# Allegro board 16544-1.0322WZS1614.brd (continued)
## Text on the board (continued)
User.36: ByImpedance:100.0@_REF_L1=("4.0/10.0(L2)" "3.5/7.0(L2)")|_REF_L6=("3.5/8.0(L5/L7)" "4.0/12.0(L5/L7)" "4.0/9.0(L4/L7)" "3.5/7.0(L4/L7)")|Type="DP"|_REF_L4=("4.0/9.0(L2/L5)" "3.5/7.0(L2/L5)")|_REF_L3=("3.5/8.0(L2/L4)" "4.0/9.0(L2/L5)" "3.5/7.0(L2/L5)" "4.0/12.0(L2/L4)")|imp="100.0"|_REF_L5=("4.0/9.0(L4/L7)" "3.5/7.0(L4/L7)")|_REF_L8=("4.0/10.0(L7)" "3.5/7.0(L7)") | ByImpedance:110.0@Type="DP"|imp="110.0" | ByImpedance:33.0@_REF_L1=("10.0(L2)")|_REF_L6=("10.5(L4/L7)" "9.5(L5/L7)")|Type="SE"|_REF_L4=("10.5(L2/L5)")|_REF_L3=("10.5(L2/L5)" "9.5(L2/L4)")|imp="33.0"|_REF_L5=("10.5(L4/L7)")|_REF_L8=("10.0(L7)") | ByImpedance:35.0@_REF_L1=("9.0(L2)")|_REF_L6=("8.5(L5/L7)" "9.5(L4/L7)")|Type="SE"|_REF_L4=("9.5(L2/L5)")|_REF_L3=("9.5(L2/L5)" "8.5(L2/L4)")|imp="35.0"|_REF_L5=("9.5(L4/L7)")|_REF_L8=("9.0(L7)") | ByImpedance:37.5@_REF_L1=("8.0(L2)")|_REF_L6=("7.5(L5/L7)" "8.5(L4/L7)")|Type="SE"|_REF_L4=("8.5(L2/L5)")|_REF_L3=("7.5(L2/L4)" "8.5(L2/L5)")|imp="37.5"|_REF_L5=("8.5(L4/L7)")|_REF_L8=("8.0(L7)") | ByImpedance:39.0@_REF_L1=("7.5(L2)")|_REF_L6=("7.0(L5/L7)" "8.0(L4/L7)")|Type="SE"|_REF_L4=("8.0(L2/L5)")|_REF_L3=("8.0(L2/L5)" "7.0(L2/L4)")|imp="39.0"|_REF_L5=("8.0(L4/L7)")|_REF_L8=("7.5(L7)") | ByImpedance:40.0@_REF_L1=("7.0(L2)")|_REF_L6=("7.5(L4/L7)" "6.5(L5/L7)")|Type="SE"|_REF_L4=("7.5(L2/L5)")|_REF_L3=("7.5(L2/L5)" "6.5(L2/L4)")|imp="40.0"|_REF_L5=("7.5(L4/L7)")|_REF_L8=("7.0(L7)") | ByImpedance:45.0@_REF_L1=("5.5(L2)")|_REF_L6=("5.0(L5/L7)" "6.0(L4/L7)")|Type="SE"|_REF_L4=("6.0(L2/L5)")|_REF_L3=("5.0(L2/L4)" "6.0(L2/L5)")|imp="45.0"|_REF_L5=("6.0(L4/L7)")|_REF_L8=("5.5(L7)") | ByImpedance:48.0@_REF_L1=("5.0(L2)")|_REF_L6=("5.0(L4/L7)" "4.5(L5/L7)")|Type="SE"|_REF_L4=("5.0(L2/L5)")|_REF_L3=("4.5(L2/L4)" "5.0(L2/L5)")|imp="48.0"|_REF_L5=("5.0(L4/L7)")|_REF_L8=("5.0(L7)") | ByImpedance:50.0@_REF_L1=("4.5(L2)")|_REF_L6=("4.0(L5/L7)" "4.5(L4/L7)")|Type="SE"|_REF_L4=("4.5(L2/L5)")|_REF_L3=("4.5(L2/L5)" "4.0(L2/L4)")|imp="50.0"|_REF_L5=("4.5(L4/L7)")|_REF_L8=("4.5(L7)") | ByImpedance:55.0@_REF_L1=("3.5(L2)")|_REF_L6=("3.5(L4/L7)")|Type="SE"|_REF_L4=("3.5(L2/L5)")|_REF_L3=("3.5(L2/L5)")|imp="55.0"|_REF_L5=("3.5(L4/L7)")|_REF_L8=("3.5(L7)") | ByImpedance:60.0@_REF_L1=("9.5/5.0(L2)")|_REF_L6=("9.5/5.0(L5/L7)" "10.0/5.0(L4/L7)")|Type="DP"|_REF_L4=("10.0/5.0(L2/L5)")|_REF_L3=("9.5/5.0(L2/L4)" "10.0/5.0(L2/L5)")|imp="60.0"|_REF_L5=("10.0/5.0(L4/L7)")|_REF_L8=("9.5/5.0(L7)") | ByImpedance:65.0@_REF_L1=("8.5/5.0(L2)")|_REF_L6=("8.5/5.0(L4/L7)" "8.0/5.0(L5/L7)")|Type="DP"|_REF_L4=("8.5/5.0(L2/L5)")|_REF_L3=("8.0/5.0(L2/L4)" "8.5/5.0(L2/L5)")|imp="65.0"|_REF_L5=("8.5/5.0(L4/L7)")|_REF_L8=("8.5/5.0(L7)") | ByImpedance:70.0@_REF_L1=("7.0/5.0(L2)")|_REF_L6=("7.0/5.0(L5/L7)" "7.5/5.0(L4/L7)")|Type="DP"|_REF_L4=("7.5/5.0(L2/L5)")|_REF_L3=("7.5/5.0(L2/L5)" "7.0/5.0(L2/L4)")|imp="70.0"|_REF_L5=("7.5/5.0(L4/L7)")|_REF_L8=("7.0/5.0(L7)") | ByImpedance:72.0@_REF_L1=("7.0/5.5(L2)")|_REF_L6=("7.0/5.0(L4/L7)" "6.5/5.0(L5/L7)")|Type="DP"|_REF_L4=("7.0/5.0(L2/L5)")|_REF_L3=("6.5/5.0(L2/L4)" "7.0/5.0(L2/L5)")|imp="72.0"|_REF_L5=("7.0/5.0(L4/L7)")|_REF_L8=("7.0/5.5(L7)") | ByImpedance:75.0@_REF_L1=("6.5/5.0(L2)")|_REF_L6=("6.0/5.0(L5/L7)" "6.5/5.0(L4/L7)")|Type="DP"|_REF_L4=("6.5/5.0(L2/L5)")|_REF_L3=("6.0/5.0(L2/L4)" "6.5/5.0(L2/L5)")|imp="75.0"|_REF_L5=("6.5/5.0(L4/L7)")|_REF_L8=("6.5/5.0(L7)") | ByImpedance:80.0@_REF_L1=("6.0/6.0(L2)" "5.0/4.5(L2)" "5.5/5.0(L2)")|_REF_L6=("5.0/5.0(L5/L7)" "5.5/5.0(L4/L7)")|Type="DP"|_REF_L4=("5.5/5.0(L2/L5)")|_REF_L3=("5.0/5.0(L2/L4)" "5.5/5.0(L2/L5)")|imp="80.0"|_REF_L5=("5.5/5.0(L4/L7)")|_REF_L8=("5.5/5.0(L7)" "6.0/6.0(L7)" "5.0/4.5(L7)") | ByImpedance:82.5@_REF_L1=("5.0/5.0(L2)")|_REF_L6=("4.5/4.5(L5/L7)")|Type="DP"|_REF_L4=("5.0/5.0(L2/L5)")|_REF_L3=("4.5/4.5(L2/L4)")|imp="82.5"|_REF_L5=("5.0/5.0(L4/L7)")|_REF_L8=("5.0/5.0(L7)") | ByImpedance:85.0@_REF_L1=("4.0/4.0(L2)" "5.0/6.0(L2)")|_REF_L6=("4.0/4.0(L4/L7)" "5.0/5.0(L4/L7)" "4.0/4.5(L5/L7)" "5.0/6.0(L5/L7)")|Type="DP"|_REF_L4=("4.0/4.0(L2/L5)" "5.0/6.0(L2/L5)")|_REF_L3=("5.0/5.0(L2/L5)" "4.0/4.0(L2/L5)" "4.0/4.5(L2/L4)" "5.0/6.0(L2/L4)")|imp="85.0"|_REF_L5=("4.0/4.0(L4/L7)" "5.0/6.0(L4/L7)")|_REF_L8=("4.0/4.0(L7)" "5.0/6.0(L7)") | ByImpedance:88.0@_REF_L1=("4.0/4.5(L2)")|_REF_L6=("4.0/4.5(L4/L7)" "4.0/5.0(L5/L7)")|Type="DP"|_REF_L4=("4.0/4.5(L2/L5)")|_REF_L3=("4.0/4.5(L2/L5)" "4.0/5.0(L2/L4)")|imp="88.0"|_REF_L5=("4.0/4.5(L4/L7)")|_REF_L8=("4.0/4.5(L7)") | ByImpedance:90.0@_REF_L1=("4.0/5.0(L2)")|_REF_L6=("4.0/6.0(L5/L7)" "4.0/5.0(L4/L7)" "5.0/7.0(L4/L7)")|Type="DP"|_REF_L4=("5.0/7.0(L2/L5)" "4.0/5.0(L2/L5)")|_REF_L3=("5.0/7.0(L2/L5)" "4.0/5.0(L2/L5)" "4.0/6.0(L2/L4)")|imp="90.0"|_REF_L5=("4.0/5.0(L4/L7)" "5.0/7.0(L4/L7)")|_REF_L8=("4.0/5.0(L7)") | LayerIndex:nil | Source:8-1.2-3k.xls | artWorks:("_REF_L3" "_REF_L6" "_REF_L5" "_REF_L4" "_REF_L8" "_REF_L1") | gtImpOutlineUsed:BOARD GEOMETRY/PANEL_OUTLINE
User.39: MB-DISPC
User.42: This gerber is just for your reference to find the DP impedance traces in layer L1. | DP IMPEDANCE TABLE: L1 | * - Denotes that this Impedance | is NOT used | IMP(Ohm) | *60.0 | *65.0 | *70.0 | 72.0 | *75.0 | *80.0 | 80.0 | *82.5 | 85.0 | *85.0 | *88.0 | 90.0 | *100.0 | WIDTH(mils) | 9.5/5.0 | 8.5/5.0 | 7.0/5.0 | 7.0/5.5 | 6.5/5.0 | 6.0/6.0 | 5.0/4.5 | 5.5/5.0 | 5.0/5.0 | 4.0/4.0 | 5.0/6.0 | 4.0/4.5 | 4.0/5.0 | 4.0/10.0 | 3.5/7.0 | TYPE | DP | Ref. Plane | L2
User.44: This gerber is just for your reference to find the SE impedance traces in layer L1. | SE IMPEDANCE TABLE: L1 | * - Denotes that this Impedance | is NOT used | IMP(Ohm) | *33.0 | *35.0 | *37.5 | *39.0 | 40.0 | *45.0 | *48.0 | 50.0 | *55.0 | WIDTH(mils) | 10.0 | 9.0 | 8.0 | 7.5 | 7.0 | 5.5 | 5.0 | 4.5 | 3.5 | TYPE | SE | Ref. Plane | L2
User.45: Note:Refer to DRILL layer for ELLIPSE drill direction | FIGURE | SIZE | 10.0 | 12.0 | 16.0 | 20.0 | 25.0 | 35.0 | 36.0 | 39.0 | 40.0 | 54.0 | 95.0 | 109.0 | 158.0 | 42.0 | 44.0 | 46.0 | 60.0 | 63.0 | 65.0 | 86.0 | 130.0 | 138.0 | 178.0 | 197.0x178.0 | DRILL CHART: TOP to BOTTOM | ALL UNITS ARE IN MILS | PLATED | NON-PLATED | QTY | 4024 | 3002 | 1553 | 40 | 7 | 8 | 14 | 38 | 23 | 2 | 1 | 3 | 5 | This gerber is just for your reference to find the DP impedance traces in layer L4. | This gerber is just for your reference to find the DP impedance traces in layer L5. | This gerber is just for your reference to find the DP impedance traces in layer L8. | This gerber is just for your reference to find the SE impedance traces in layer L3. | This gerber is just for your reference to find the SE impedance traces in layer L4. | This gerber is just for your reference to find the SE impedance traces in layer L5. | This gerber is just for your reference to find the SE impedance traces in layer L6. | This gerber is just for your reference to find the SE impedance traces in layer L8. | This gerber is just for your reference to find the DP impedance traces in layer L3. | This gerber is just for your reference to find the DP impedance traces in layer L6. | DP IMPEDANCE TABLE: L3 | DP IMPEDANCE TABLE: L4 | DP IMPEDANCE TABLE: L5 | DP IMPEDANCE TABLE: L6 | DP IMPEDANCE TABLE: L8 | SE IMPEDANCE TABLE: L3 | SE IMPEDANCE TABLE: L4 | SE IMPEDANCE TABLE: L5 | SE IMPEDANCE TABLE: L6 | SE IMPEDANCE TABLE: L8 | * - Denotes that this Impedance | is NOT used | Model | PASR/CY17 Thanos | PCB_NO | 16544 | VER. | Layer | DRILL | L1 | L2GND | L3 | L4 | TMASK | TPLACE | TSILK | TSMD | Designer | CLAIRE | Date | 03/22/2017 | IMP(Ohm) | *33.0 | *60.0 | *35.0 | *65.0 | *37.5 | *70.0 | *39.0 | *72.0 | *40.0 | *75.0 | *45.0 | *80.0 | 80.0 | *48.0 | *82.5 | *50.0 | *85.0 | 50.0 | 72.0 | 85.0 | *55.0 | *88.0 | *90.0 | 90.0 | *100.0 | WIDTH(mils) | 9.0 | 8.0 | 7.5 | 7.0 | 5.5 | 5.0 | 4.5 | 3.5 | 10.5 | 9.5 | 8.5 | 6.0 | 6.5 | 4.0 | 9.5/5.0 | 8.5/5.0 | 7.0/5.0 | 7.0/5.5 | 6.5/5.0 | 5.5/5.0 | 6.0/6.0 | 5.0/4.5 | 5.0/5.0 | 4.0/4.0 | 5.0/6.0 | 4.0/4.5 | 4.0/5.0 | 4.0/10.0 | 3.5/7.0 | 10.0/5.0 | 7.5/5.0 | 8.0/5.0 | 6.0/5.0 | 5.0/7.0 | 4.0/9.0 | 4.5/4.5 | 4.0/6.0 | 3.5/8.0 | 4.0/12.0 | TYPE | SE | DP | Ref. Plane | L7 | L2/L5 | L4/L7 | L2/L4 | L5/L7 | BMASK | BPLACE | BSILK | BSMD | L5GND | L6 | L7GND | L8
